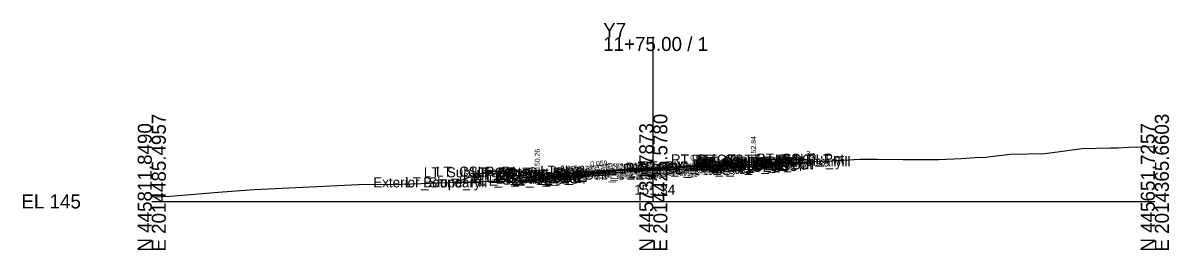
# Model space of a CAD drawing. Extents: x -26 to 203, y -10 to 7527.
# Drawn here: x -25.7 to 202.8, y 3490.3 to 3535.6 of the extents above; entities that cross this region are included whole.
import ezdxf

# ---------------------------------------------------------------- set-up
doc = ezdxf.new("R2010")
doc.units = 0
for name, color, linetype in [('Exist CMT Pavement', 7, 'Continuous'), ('Exist Cross Section Cell', 7, 'Continuous'), ('Exist XS Center Line Elevation Label', 7, 'Continuous'), ('Exist XS Ground Line', 7, 'Continuous'), ('Prop CMT Conc Surface', 7, 'Continuous'), ('Prop CMT Concrete Structures', 7, 'Continuous'), ('Prop CMT Pvmt Course 1', 7, 'Continuous'), ('Prop CMT Pvmt Course 1 CG', 7, 'Continuous'), ('Prop CMT Pvmt Course 1 Wedge', 7, 'Continuous'), ('Prop CMT Pvmt Course 2', 7, 'Continuous'), ('Prop CMT Pvmt Course 2 Wedge', 7, 'Continuous'), ('Prop CMT Pvmt Course 3', 7, 'Continuous'), ('Prop CMT Pvmt Course 3 Wedge', 7, 'Continuous'), ('Prop CMT Pvmt Surface', 7, 'Continuous'), ('Prop CMT Pvmt Wedge Surface 1', 7, 'Continuous'), ('Prop CMT Pvmt Wedge Surface 2', 7, 'Continuous'), ('Prop CMT Pvmt Wedge Surface 3', 7, 'Continuous'), ('Prop CMT Slope Grass', 7, 'Continuous'), ('Prop CMT Subgrade Earthwork', 7, 'Continuous'), ('Prop XS Earthwork Shape', 7, 'Continuous'), ('Prop XS Hydro Elevations', 7, 'Continuous'), ('Prop XS SE Text', 7, 'Continuous'), ('Prop XS Side Slope Text', 7, 'Continuous'), ('Prop XS Wedging', 7, 'Continuous'), ('Scratch_Level_0', 7, 'Continuous')]:
    doc.layers.add(name, color=color, linetype=linetype)

msp = doc.modelspace()

# ---------------------------------------------------------------- linework, layer by layer
at = {"layer": 'Exist CMT Pavement'}
msp.add_lwpolyline([(92.48, 3506.14), (92.48, 3506.14), (96.27, 3506.24), (99.94, 3506.34), (101.69, 3506.34), (107.46, 3506.5)], dxfattribs=at)
at = {"layer": 'Exist Cross Section Cell'}
for p, q in [((100, 3500), (100, 3532.79)), ((0, 3500), (100, 3500)), ((100, 3500), (200, 3500))]:
    msp.add_line(p, q, dxfattribs=at)
at = {"layer": 'Exist XS Ground Line'}
msp.add_lwpolyline([(0, 3500.91), (3.75, 3501.05), (14.07, 3501.93), (20.43, 3502.37), (41.22, 3503.39), (49.79, 3503.47), (53.71, 3503.6), (56.94, 3503.71), (66.2, 3503.98), (71.89, 3504.14), (79.18, 3504.29), (79.76, 3504.32), (81.8, 3504.59), (92.48, 3506.14), (96.27, 3506.24), (99.94, 3506.34), (101.69, 3506.34), (107.46, 3506.5), (109.32, 3506.77), (111.59, 3507), (112.1, 3506.64), (114.29, 3505.98), (116.46, 3506.15), (117.22, 3506.16), (118.12, 3507.3), (127.35, 3507.77), (128.67, 3507.82), (135.53, 3508.13), (141.16, 3508.42), (142.67, 3508.43), (144.7, 3508.44), (149.82, 3508.34), (153.65, 3508.36), (156.96, 3508.38), (161.39, 3508.56), (164.11, 3508.77), (166.14, 3508.85), (171.25, 3509.41), (178.08, 3509.58), (178.63, 3509.62), (185.54, 3510.57), (191.13, 3510.68), (192.69, 3510.66), (194.77, 3510.84), (200, 3510.93)], dxfattribs=at)
at = {"layer": 'Prop CMT Conc Surface'}
for points in [[(119.97, 3507.81), (119.97, 3508.31), (120.47, 3508.31)], [(76.86, 3505.28), (76.86, 3505.78), (76.36, 3505.78)], [(117.97, 3507.77), (119.97, 3507.81)], [(78.86, 3505.48), (76.86, 3505.28)]]:
    msp.add_lwpolyline(points, dxfattribs=at)
at = {"layer": 'Prop CMT Concrete Structures'}
for points in [[(117.97, 3507.77), (119.97, 3507.81), (119.97, 3508.31), (120.47, 3508.31)], [(120.47, 3508.31), (120.47, 3507.34), (117.97, 3507.19)], [(78.86, 3505.48), (76.86, 3505.28), (76.86, 3505.78), (76.36, 3505.78)], [(76.36, 3505.78), (76.36, 3504.75), (78.86, 3504.89)], [(117.97, 3507.19), (117.97, 3507.77)], [(78.86, 3504.89), (78.86, 3505.48)]]:
    msp.add_lwpolyline(points, dxfattribs=at)
at = {"layer": 'Prop CMT Pvmt Course 1'}
for points in [[(100, 3506.72), (78.86, 3505.48)], [(78.86, 3505.23), (92.48, 3506.03)], [(92.48, 3506.15), (100, 3506.59)], [(92.48, 3506.03), (92.48, 3506.15)], [(100, 3506.72), (117.97, 3507.77)], [(107.46, 3507.03), (100, 3506.59)], [(100, 3506.47), (100, 3506.72)], [(100, 3506.47), (100, 3506.72)], [(100, 3506.59), (100, 3506.47), (100, 3506.47)], [(100, 3506.59), (100, 3506.47), (100, 3506.47)], [(117.97, 3507.52), (107.46, 3506.91)], [(107.46, 3506.91), (107.46, 3507.03)], [(117.97, 3507.77), (117.97, 3507.52)], [(78.86, 3505.48), (78.86, 3505.23)]]:
    msp.add_lwpolyline(points, dxfattribs=at)
at = {"layer": 'Prop CMT Pvmt Course 1 CG'}
for points in [[(117.97, 3507.19), (120.97, 3507.37), (121.28, 3507.05)], [(117.97, 3506.86), (117.97, 3507.19)], [(121.28, 3507.05), (117.97, 3506.86)], [(78.86, 3504.89), (75.86, 3504.72), (75.51, 3504.37)], [(75.51, 3504.37), (78.86, 3504.56)], [(78.86, 3504.56), (78.86, 3504.89)]]:
    msp.add_lwpolyline(points, dxfattribs=at)
at = {"layer": 'Prop CMT Pvmt Course 1 Wedge'}
for points in [[(100, 3506.59), (92.48, 3506.15)], [(100, 3506.59), (107.46, 3507.03)]]:
    msp.add_lwpolyline(points, dxfattribs=at)
at = {"layer": 'Prop CMT Pvmt Course 2'}
for points in [[(92.48, 3506.03), (78.86, 3505.23)], [(78.86, 3504.89), (92.48, 3505.7)], [(92.48, 3505.7), (92.48, 3506.03)], [(107.46, 3506.91), (117.97, 3507.52)], [(117.97, 3507.19), (107.46, 3506.57)], [(107.46, 3506.57), (107.46, 3506.91)], [(117.97, 3507.52), (117.97, 3507.19)], [(78.86, 3505.23), (78.86, 3504.89)]]:
    msp.add_lwpolyline(points, dxfattribs=at)
at = {"layer": 'Prop CMT Pvmt Course 2 Wedge'}
for points in [[(100, 3506.47), (92.48, 3506.03)], [(100, 3506.47), (107.46, 3506.91)]]:
    msp.add_lwpolyline(points, dxfattribs=at)
at = {"layer": 'Prop CMT Pvmt Course 3'}
for points in [[(92.48, 3505.7), (78.86, 3504.89)], [(92.48, 3505.36), (92.48, 3505.7)], [(107.46, 3506.57), (117.97, 3507.19)], [(117.97, 3506.86), (107.46, 3506.24)], [(107.46, 3506.24), (107.46, 3506.57)], [(117.97, 3507.19), (117.97, 3506.86)], [(78.86, 3504.56), (92.48, 3505.36)], [(78.86, 3504.89), (78.86, 3504.56)]]:
    msp.add_lwpolyline(points, dxfattribs=at)
at = {"layer": 'Prop CMT Pvmt Course 3 Wedge'}
for points in [[(100, 3506.14), (92.48, 3505.7)], [(100, 3506.14), (107.46, 3506.57)]]:
    msp.add_lwpolyline(points, dxfattribs=at)
at = {"layer": 'Prop CMT Pvmt Surface'}
for points in [[(100, 3506.72), (78.86, 3505.48)], [(100, 3506.72), (117.97, 3507.77)]]:
    msp.add_lwpolyline(points, dxfattribs=at)
at = {"layer": 'Prop CMT Pvmt Wedge Surface 1'}
for points in [[(92.48, 3506.03), (78.86, 3505.23)], [(100, 3506.59), (92.48, 3506.15)], [(92.48, 3506.15), (92.48, 3506.03)], [(100, 3506.59), (107.46, 3507.03)], [(107.46, 3506.91), (117.97, 3507.52)], [(107.46, 3507.03), (107.46, 3506.91)], [(117.97, 3507.52), (117.97, 3507.77)], [(78.86, 3505.23), (78.86, 3505.48)]]:
    msp.add_lwpolyline(points, dxfattribs=at)
at = {"layer": 'Prop CMT Pvmt Wedge Surface 2'}
for points in [[(100, 3506.47), (78.86, 3505.23)], [(100, 3506.47), (117.97, 3507.52)], [(117.97, 3507.52), (117.97, 3507.77)], [(78.86, 3505.23), (78.86, 3505.48)]]:
    msp.add_lwpolyline(points, dxfattribs=at)
at = {"layer": 'Prop CMT Pvmt Wedge Surface 3'}
for points in [[(100, 3506.14), (78.86, 3504.89)], [(100, 3506.14), (117.97, 3507.19)], [(117.97, 3507.19), (117.97, 3507.77)], [(78.86, 3504.89), (78.86, 3505.48)]]:
    msp.add_lwpolyline(points, dxfattribs=at)
at = {"layer": 'Prop CMT Slope Grass'}
for points in [[(120.47, 3508.31), (129.97, 3508.5), (131.61, 3507.95)], [(76.36, 3505.78), (66.86, 3505.97), (60.38, 3503.81)]]:
    msp.add_lwpolyline(points, dxfattribs=at)
at = {"layer": 'Prop CMT Subgrade Earthwork'}
for points in [[(117.97, 3506.86), (121.28, 3507.05), (122.59, 3508.35)], [(78.86, 3504.56), (75.51, 3504.37), (74.04, 3505.83)], [(92.48, 3505.36), (92.48, 3506.14)], [(107.46, 3506.24), (117.97, 3506.86)], [(107.46, 3506.24), (107.46, 3506.5)], [(92.48, 3505.36), (78.86, 3504.56)]]:
    msp.add_lwpolyline(points, dxfattribs=at)
at = {"layer": 'Prop XS Earthwork Shape'}
for points in [[(128.67, 3507.82), (131.61, 3507.95), (129.97, 3508.5), (122.59, 3508.35), (121.71, 3507.48), (127.35, 3507.77)], [(78.86, 3504.56), (75.51, 3504.37), (74.04, 3505.83), (66.86, 3505.97), (60.38, 3503.81), (66.2, 3503.98), (71.89, 3504.14), (79.18, 3504.29), (79.76, 3504.32), (81.8, 3504.59), (83.51, 3504.83)], [(92.48, 3505.36), (92.48, 3506.14), (83.51, 3504.83)], [(112.1, 3506.64), (112.45, 3506.53), (107.46, 3506.24), (107.46, 3506.5), (109.32, 3506.77), (111.59, 3507)], [(116.46, 3506.15), (117.22, 3506.16), (117.76, 3506.85), (112.45, 3506.53), (114.29, 3505.98)], [(120.47, 3507.42), (121.71, 3507.48), (121.28, 3507.05), (117.97, 3506.86), (117.76, 3506.85), (118.04, 3507.2), (120.47, 3507.34)], [(120.47, 3507.34), (118.04, 3507.2), (118.12, 3507.3), (120.47, 3507.42)]]:
    msp.add_lwpolyline(points, close=True, dxfattribs=at)
at = {"layer": 'Prop XS Wedging'}
msp.add_line((101.32, 3506.34), (101.55, 3506.56), dxfattribs=at)

# ---------------------------------------------------------------- texts
at = {"layer": 'Exist Cross Section Cell'}
for s, p in [('Y7', (90, 3532.79)), ('11+75.00 / 1', (90, 3529.99)), ('EL 145', (-26, 3498.6))]:
    msp.add_text(s, height=2.8, dxfattribs=at).set_placement(p)
for s, p in [('E 2014485.4957', (2.8, 3490)), ('E 2014425.5780', (102.8, 3490)), ('E 2014365.6603', (202.8, 3490)), ('N 445811.8490', (0, 3490)), ('N 445731.7873', (100, 3490)), ('N 445651.7257', (200, 3490))]:
    msp.add_text(s, height=2.8, rotation=90, dxfattribs=at).set_placement(p)
at = {"layer": 'Exist XS Center Line Elevation Label'}
msp.add_text('151.34', height=2, dxfattribs=at).set_placement((96.2, 3501.34))
at = {"layer": 'Prop XS Hydro Elevations'}
for s, p in [('152.84', (120.47, 3508.81)), ('150.26', (77.36, 3506.28))]:
    msp.add_text(s, height=1, rotation=90, dxfattribs=at).set_placement(p)
at = {"layer": 'Prop XS SE Text'}
for rotation, p in [(3.3611, (87.45, 3506.98)), (3.3597, (107.4, 3508.16))]:
    msp.add_text('0.059', height=1, rotation=rotation, dxfattribs=at).set_placement(p)
at = {"layer": 'Prop XS Side Slope Text'}
for rotation, p in [(341.5668, (130.28, 3509.19)), (18.4332, (62.64, 3505.36))]:
    msp.add_text('3:1', height=1, rotation=rotation, dxfattribs=at).set_placement(p)
at = {"layer": 'Scratch_Level_0'}
for s, p in [('RT_PV1_OEEOP', (97.28, 3506.03)), ('RT_Sub_Trench_Out_DLT', (103.52, 3507.38)), ('RT_CG_Top_Face', (107.6, 3507.34)), ('RT_CG1_Shelf_Out', (107.89, 3506.39)), ('RT_CG_Bot_IE', (108.25, 3506.22)), ('RT_Sub_OEOT', (108.42, 3505.88)), ('RT_PV2_OEOT', (108.51, 3506.55)), ('RT_PV3_OEOT', (108.51, 3506.22)), ('RT_CG_Top_Gut', (108.58, 3506.84)), ('RT_PV1_OEOT', (109.08, 3506.8)), ('RT_CG_Top_BOC', (109.12, 3507.34)), ('RT_CG_Bot_BOC', (109.15, 3506.36)), ('RT_Sub_OEOP', (111.76, 3506.08)), ('Exterior Boundary', (116.18, 3506.98)), ('RT_CSLP_Pnt', (120.51, 3507.53)), ('RT_Slope_Fill', (122.51, 3506.98)), ('LT_Sub_Trench_Out_DLT', (54.23, 3504.81)), ('LT_CSLP_Pnt', (56.66, 3504.95)), ('LT_CG1_Shelf_Out', (62.03, 3503.7)), ('LT_CG_Top_Face', (63.74, 3504.76)), ('LT_CG_Top_BOC', (64.27, 3504.76)), ('LT_CG_Bot_BOC', (64.3, 3503.73)), ('LT_CG_Top_Gut', (64.72, 3504.26)), ('LT_CG_Bot_IE', (68.4, 3503.87)), ('LT_PV2_OEOT', (68.66, 3504.21)), ('LT_PV3_OEOT', (68.66, 3503.87)), ('LT_PV1_OEOT', (69.22, 3504.46)), ('LT_PV_Sub_Tie_Out', (77.44, 3505.14)), ('LT_PV_OEEOP_EG', (80.03, 3505.14)), ('LT_Sub_OEEOP', (81.69, 3504.36)), ('LT_PV2_OEEOP', (81.79, 3505.03)), ('LT_PV3_OEEOP', (81.79, 3504.7)), ('LT_PV1_OEEOP', (82.36, 3505.15)), ('RT_PV_IEEOP_EG', (88.14, 3505.34)), ('LT_PV_IEEOP_EG', (88.19, 3505.34)), ('RT_PV2_IEEOP', (89.91, 3505.47)), ('RT_PV3_IEEOP', (89.91, 3505.14)), ('LT_PV2_IEEOP', (89.95, 3505.47)), ('LT_PV3_IEEOP', (89.95, 3505.14)), ('RT_PV1_IEEOP', (90.47, 3505.59)), ('LT_PV1_IEEOP', (90.52, 3505.59)), ('RT_PV_Sub_Tie_Out', (92.34, 3505.5)), ('PV2_PGL', (93.91, 3505.47)), ('PV1_PGL', (94.47, 3505.72)), ('RT_PV_OEEOP_EG', (94.95, 3505.5)), ('RT_Sub_OEEOP', (96.62, 3505.24)), ('RT_PV2_OEEOP', (96.71, 3505.91)), ('RT_PV3_OEEOP', (96.71, 3505.57)), ('Exterior Boundary', (44.17, 3502.8)), ('LT_Slope_Fill', (50.55, 3502.8)), ('LT_Sub_OEOP', (65.24, 3503.34)), ('LT_Sub_OEOT', (68.56, 3503.54))]:
    msp.add_text(s, height=2, dxfattribs=at).set_placement(p)

doc.saveas('drawing.dxf')
